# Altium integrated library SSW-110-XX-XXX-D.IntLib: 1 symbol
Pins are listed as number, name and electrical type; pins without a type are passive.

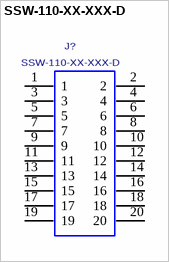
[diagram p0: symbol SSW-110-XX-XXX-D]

## SSW-110-XX-XXX-D
designator J?
ASSEMBLY, SOCKET STRIP .016 X .031 TAIL, 20 PINS.; MANUFACTURER: SAMTEC
footprint SSW-110-XX-XXX-D
pins: 1, 2, 3, 4, 5, 6, 7, 8, 9, 10, 11, 12, 13, 14, 15, 16, 17, 18, 19, 20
